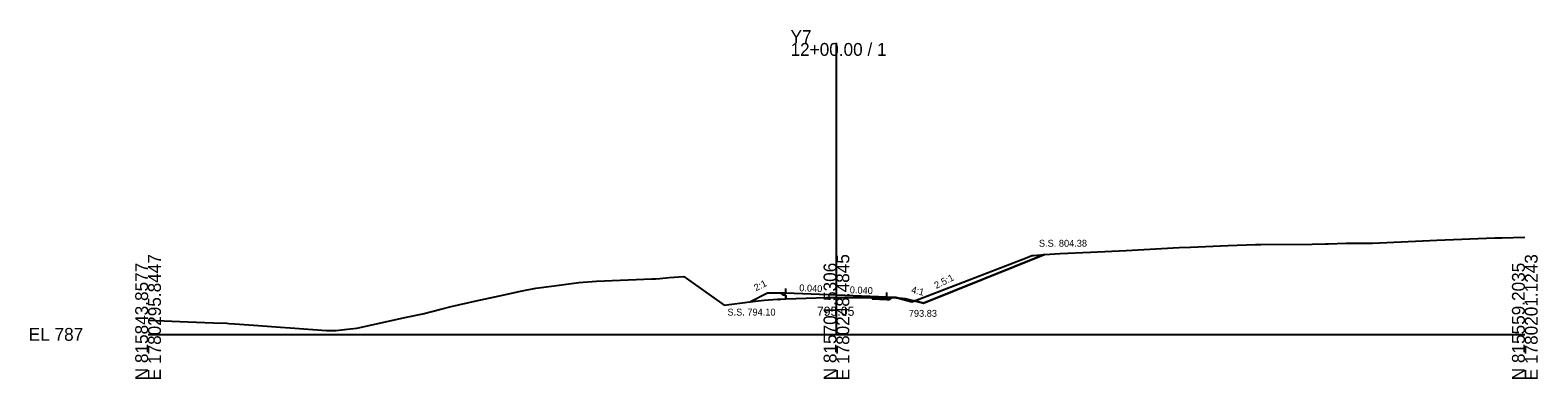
# Model space of a CAD drawing. Extents: x -26 to 2903, y -10 to 5536.
# Drawn here: x -25.7 to 302.8, y 1990.3 to 2066.3 of the extents above; entities that cross this region are included whole.
import ezdxf

# ---------------------------------------------------------------- set-up
doc = ezdxf.new("R2010")
doc.units = 0
for name, color, linetype in [('Exist Cross Section Cell', 7, 'Continuous'), ('Exist XS Center Line Elevation Label', 7, 'Continuous'), ('Exist XS Ground Line', 7, 'Continuous'), ('Prop XS Ditch Slope Text', 7, 'Continuous'), ('Prop XS Ditch Standard Text', 7, 'Continuous'), ('Prop XS Dump Level', 7, 'Continuous'), ('Prop XS Earthwork Shape', 7, 'Continuous'), ('Prop XS EOT Tick Mark', 7, 'Continuous'), ('Prop XS Finish Grade', 7, 'Continuous'), ('Prop XS Finish Grade Earthwork', 7, 'Continuous'), ('Prop XS Finish Grade Pavement', 7, 'Continuous'), ('Prop XS Pvmt Edge Slope', 7, 'Continuous'), ('Prop XS SE Text', 7, 'Continuous'), ('Prop XS Side Slope Text', 7, 'Continuous'), ('Prop XS SS Elevation Text', 7, 'Continuous'), ('Prop XS Subgrade Earthwork', 7, 'Continuous')]:
    doc.layers.add(name, color=color, linetype=linetype)

msp = doc.modelspace()

# ---------------------------------------------------------------- linework, layer by layer
at = {"layer": 'Exist Cross Section Cell'}
for p, q in [((150, 2000), (150, 2063.5)), ((0, 2000), (150, 2000)), ((150, 2000), (300, 2000))]:
    msp.add_line(p, q, dxfattribs=at)
at = {"layer": 'Exist XS Ground Line'}
for p, q in [((266.8, 2019.91), (280.8, 2020.56)), ((280.8, 2020.56), (293.5, 2021.01)), ((293.5, 2021.01), (294.97, 2021.05)), ((294.97, 2021.05), (300, 2021.17)), ((191.56, 2016.72), (192.57, 2017.22)), ((192.57, 2017.22), (192.95, 2017.22)), ((192.95, 2017.22), (195.32, 2017.37)), ((195.32, 2017.37), (198.74, 2017.6)), ((198.74, 2017.6), (205.36, 2017.93)), ((205.36, 2017.93), (213.1, 2018.26)), ((213.1, 2018.26), (224.68, 2018.91)), ((224.68, 2018.91), (227.15, 2019.01)), ((227.15, 2019.01), (235.35, 2019.37)), ((235.35, 2019.37), (241.35, 2019.6)), ((241.35, 2019.6), (242.49, 2019.61)), ((242.49, 2019.61), (253.68, 2019.67)), ((253.68, 2019.67), (256.6, 2019.7)), ((256.6, 2019.7), (257.25, 2019.74)), ((257.25, 2019.74), (260.97, 2019.85)), ((260.97, 2019.85), (266.8, 2019.91)), ((166.9, 2007.27), (191.56, 2016.72)), ((88.49, 2010.55), (93.84, 2011.28)), ((93.84, 2011.28), (97.69, 2011.56)), ((97.69, 2011.56), (109.74, 2012.11)), ((109.74, 2012.11), (110.62, 2012.13)), ((110.62, 2012.13), (111.51, 2012.14)), ((111.51, 2012.14), (113.56, 2012.39)), ((113.56, 2012.39), (116.73, 2012.59)), ((116.73, 2012.59), (118.28, 2011.52)), ((118.28, 2011.52), (125.52, 2006.38)), ((71.48, 2007.3), (76.58, 2008.41)), ((76.58, 2008.41), (81.51, 2009.5)), ((81.51, 2009.5), (84.51, 2010.04)), ((84.51, 2010.04), (88.49, 2010.55)), ((132.28, 2007.22), (134.24, 2007.42)), ((134.24, 2007.42), (137.13, 2007.65)), ((137.13, 2007.65), (138.94, 2007.77)), ((138.94, 2007.77), (147.85, 2008.06)), ((147.85, 2008.06), (148.21, 2008.06)), ((148.21, 2008.06), (148.6, 2008.06)), ((148.6, 2008.06), (150, 2008.05)), ((150, 2008.05), (157.78, 2008.03)), ((157.78, 2008.03), (158.7, 2008.08)), ((158.7, 2008.08), (160.81, 2008.09)), ((160.81, 2008.09), (162.38, 2008.11)), ((162.38, 2008.11), (163.76, 2007.81)), ((163.76, 2007.81), (166.44, 2007.09)), ((56.29, 2003.72), (59.9, 2004.51)), ((59.9, 2004.51), (63.8, 2005.52)), ((63.8, 2005.52), (66.06, 2006.11)), ((66.06, 2006.11), (71.48, 2007.3)), ((125.52, 2006.38), (131.13, 2007.08)), ((131.13, 2007.08), (132.28, 2007.22)), ((166.44, 2007.09), (166.9, 2007.27)), ((0, 2003.06), (8.69, 2002.73)), ((8.69, 2002.73), (14.26, 2002.52)), ((14.26, 2002.52), (17.18, 2002.41)), ((17.18, 2002.41), (17.59, 2002.39)), ((17.59, 2002.39), (18.89, 2002.32)), ((18.89, 2002.32), (23.99, 2001.93)), ((23.99, 2001.93), (28.83, 2001.6)), ((28.83, 2001.6), (30.93, 2001.42)), ((30.93, 2001.42), (38.88, 2000.83)), ((38.88, 2000.83), (40.9, 2000.83)), ((40.9, 2000.83), (44.09, 2001.18)), ((44.09, 2001.18), (45.49, 2001.34)), ((45.49, 2001.34), (56.29, 2003.72))]:
    msp.add_line(p, q, dxfattribs=at)
at = {"layer": 'Prop XS Dump Level'}
for p, q in [((139, 2009.03), (150, 2008.59)), ((150, 2008.59), (161, 2008.15))]:
    msp.add_line(p, q, dxfattribs=at)
at = {"layer": 'Prop XS Earthwork Shape'}
for points in [[(167.04, 2007.32), (191.56, 2016.72), (192.57, 2017.22), (192.95, 2017.22), (195.32, 2017.37), (195.37, 2017.38), (169, 2006.83)], [(135, 2008.95), (131.3, 2007.1), (132.28, 2007.22), (134.24, 2007.42), (137.13, 2007.65), (138.94, 2007.77), (139, 2007.77), (139, 2008.49), (138.48, 2008.51), (137.98, 2009.01)], [(157.78, 2007.74), (157.78, 2008.03), (158.7, 2008.08), (160.81, 2008.09), (162.38, 2008.11), (162.91, 2008), (162.04, 2008.07), (161.56, 2007.58), (161, 2007.61)], [(165, 2007.83), (167.04, 2007.32), (166.9, 2007.27), (166.44, 2007.09), (163.76, 2007.81), (162.91, 2008)]]:
    msp.add_lwpolyline(points, close=True, dxfattribs=at)
at = {"layer": 'Prop XS EOT Tick Mark'}
for p, q in [((139, 2009.03), (139, 2010.03)), ((161, 2008.15), (161, 2009.15))]:
    msp.add_line(p, q, dxfattribs=at)
at = {"layer": 'Prop XS Finish Grade'}
for p, q in [((139, 2009.03), (137.98, 2009.01)), ((161, 2008.15), (162.04, 2008.07))]:
    msp.add_line(p, q, dxfattribs=at)
at = {"layer": 'Prop XS Finish Grade Earthwork'}
for p, q in [((169, 2006.83), (195.37, 2017.38)), ((135, 2008.95), (131.3, 2007.1)), ((137.98, 2009.01), (135, 2008.95)), ((162.04, 2008.07), (165, 2007.83)), ((165, 2007.83), (169, 2006.83))]:
    msp.add_line(p, q, dxfattribs=at)
at = {"layer": 'Prop XS Finish Grade Pavement'}
for p, q in [((139, 2009.03), (150, 2008.59)), ((150, 2008.59), (161, 2008.15))]:
    msp.add_line(p, q, dxfattribs=at)
at = {"layer": 'Prop XS Pvmt Edge Slope'}
for p, q in [((139, 2009.03), (138.48, 2008.51)), ((161, 2008.15), (161.56, 2007.58))]:
    msp.add_line(p, q, dxfattribs=at)
at = {"layer": 'Prop XS Subgrade Earthwork'}
for p, q in [((138.48, 2008.51), (137.98, 2009.01)), ((139, 2008.49), (138.48, 2008.51)), ((139, 2008.49), (139, 2007.77)), ((157.78, 2007.74), (157.78, 2008.03)), ((157.78, 2007.74), (161, 2007.61)), ((161, 2007.61), (161.56, 2007.58)), ((161.56, 2007.58), (162.04, 2008.07))]:
    msp.add_line(p, q, dxfattribs=at)

# ---------------------------------------------------------------- texts
at = {"layer": 'Exist Cross Section Cell'}
for s, p in [('Y7', (140, 2063.5)), ('12+00.00 / 1', (140, 2060.7)), ('EL 787', (-26, 1998.6))]:
    msp.add_text(s, height=2.8, dxfattribs=at).set_placement(p)
for s, p in [('E 1780295.8447', (2.8, 1990)), ('E 1780248.4845', (152.8, 1990)), ('E 1780201.1243', (302.8, 1990)), ('N 815843.8577', (0, 1990)), ('N 815701.5306', (150, 1990)), ('N 815559.2035', (300, 1990))]:
    msp.add_text(s, height=2.8, rotation=90, dxfattribs=at).set_placement(p)
at = {"layer": 'Exist XS Center Line Elevation Label'}
msp.add_text('795.05', height=2, dxfattribs=at).set_placement((145.74, 2004.05))
at = {"layer": 'Prop XS Ditch Slope Text'}
msp.add_text('4:1', height=1.5, rotation=345.9638, dxfattribs=at).set_placement((166.19, 2009.08))
at = {"layer": 'Prop XS Ditch Standard Text'}
msp.add_text('793.83', height=1.5, dxfattribs=at).set_placement((165.77, 2003.83))
at = {"layer": 'Prop XS Dump Level'}
for s, height, p in [('Case1', 0.04, (135, 2008.91)), ('Eop', 0.3, (137.13, 2007.35)), ('Eop', 0.3, (157.78, 2007.73)), ('Case1', 0.04, (165, 2007.79))]:
    msp.add_text(s, height=height, dxfattribs=at).set_placement(p)
at = {"layer": 'Prop XS SE Text'}
for p in [(141.88, 2009.41), (152.88, 2008.97)]:
    msp.add_text('0.040', height=1.5, rotation=357.7094, dxfattribs=at).set_placement(p)
at = {"layer": 'Prop XS Side Slope Text'}
for s, p in [('2:1', (132.48, 2009.37)), ('2.5:1', (171.77, 2009.89))]:
    msp.add_text(s, height=1.5, rotation=26.5651, dxfattribs=at).set_placement(p)
at = {"layer": 'Prop XS SS Elevation Text'}
for s, p in [('S.S. 804.38', (194.12, 2019.1)), ('S.S. 794.10', (126.25, 2004.1))]:
    msp.add_text(s, height=1.5, dxfattribs=at).set_placement(p)

doc.saveas('drawing.dxf')
